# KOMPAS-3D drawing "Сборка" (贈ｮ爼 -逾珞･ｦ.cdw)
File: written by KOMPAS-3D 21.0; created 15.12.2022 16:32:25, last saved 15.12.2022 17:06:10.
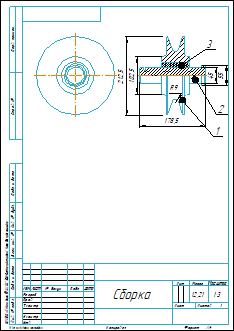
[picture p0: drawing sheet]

Sheet 1: A4, portrait

Document properties: Автор: gggchaseggg@gmail.com; Масса: 12.207336

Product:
- Part/product: Сборка
    Масса: 12.207336
    Форматы листов документа: A4
    source file: Сборка-спецификация.spw
  - Component [detail]: Ось  | pos. 2  | Масса: 2.283245; source file: Bolt.m3d
  - Component [detail]: Втулка  | pos. 3  | Масса: 1.321575; source file: Vtulka.m3d
  - Component [detail]: Ролик  | pos. 1  | Масса: 8.602516; source file: Rolik.m3d

Title block, sheet 1: Наименование: Сборка; Масса: 12,21; Количество листов документа: 1; Форматы листов документа: A4; stored path: C:\git\VlSU\IGS(AutoCAD)\rk3\Сборка-чертеж.cdw

Views: Вид 1, Спереди, Проекционный вид 2, Местный разрез 1
Referenced files in C:\git\VlSU\IGS(AutoCAD)\rk3\: Сборка.a3d, Rolik.m3d, Vtulka.m3d, Bolt.m3d
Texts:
  Ролик
  Ось
  Втулка
Dimensions and other numbers on the sheet: 178,5; 212,5; 45; 55; 9; 102,5; 2; 1; 3; 1:3; 12,21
